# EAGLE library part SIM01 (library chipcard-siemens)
Siemens M20 CHIP CARD READER
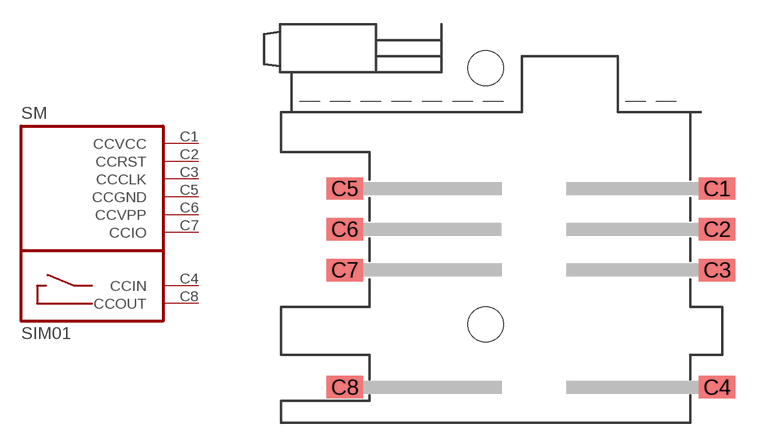
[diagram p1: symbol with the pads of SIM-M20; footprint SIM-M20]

Designator prefix SM

## SIM01 (OC_FARNELL: unknown; OC_NEWARK: unknown)  [SIM-M20]
C1  CCVCC  pas
C2  CCRST  pas
C3  CCCLK  pas
C4  CCIN  pas
C5  CCGND  pas
C6  CCVPP  pas
C7  CCIO  pas
C8  CCOUT  pas

## Footprint SIM-M20 (pad centres in mm)
Siemens M20 CHIP CARD READER SIM-Kartenleser für SIEMENS Modul M20 91228-0001 SIM PCB CONNECTOR von MOLEX
smd 2.286 x 1.397: C1 11.43,2.235; C2 11.43,-0.305; C3 11.43,-2.845; C4 11.43,-10.16; C5 -11.786,2.235; C6 -11.786,-0.305; C7 -11.786,-2.845; C8 -11.786,-10.16
hole 2.184 at -3.004,9.75
hole 2.184 at -3.004,-6.25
